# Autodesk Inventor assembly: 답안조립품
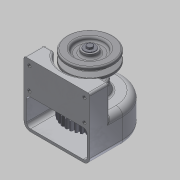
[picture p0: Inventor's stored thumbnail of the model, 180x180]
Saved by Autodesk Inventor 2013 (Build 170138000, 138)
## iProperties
Created: 2015-02
Part Number: 답안조립품
Document SubType Name: Assembly
Designer: Administrator
Author: Administrator
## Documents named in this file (14)
- C:\Users\Administrator\Desktop\450216V1013\답안조립품.iam
- C:\Users\Administrator\Desktop\450216V1013\본체.ipt
- C:\Users\Administrator\Desktop\450216V1013\축커버.ipt
- C:\Users\Administrator\Desktop\450216V1013\베어링 6001.ipt
- C:\Users\Administrator\Desktop\450216V1013\오일실.ipt
- C:\Users\Administrator\Desktop\450216V1013\M3x0.5.ipt
- C:\Users\Administrator\Desktop\450216V1013\축.ipt
- C:\Users\Administrator\Desktop\450216V1013\키4x4.ipt
- C:\Users\Administrator\Desktop\450216V1013\키5x5.ipt
- C:\Users\Administrator\Desktop\450216V1013\스퍼기어.ipt
- C:\Users\Administrator\Desktop\450216V1013\V-벨트풀리.ipt
- C:\Users\Administrator\Desktop\450216V1013\M5x0.8.ipt
- M5x0.8.ipt
- C:\Users\Administrator\Desktop\450216V1013\와샤.ipt
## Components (6 placed, 3 different names)
1. V-벨트풀리:1 — 각도:2, 플러쉬:1, 각도:3
2. M5x0.8:1 — 각도:3
3. M3x0.5:1
4. M3x0.5:2
5. M3x0.5:3
6. M3x0.5:4
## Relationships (3: Angle 2, Flush 1)
- 각도:2 [Angle]: V-벨트풀리:1
- 플러쉬:1 [Flush]: V-벨트풀리:1
- 각도:3 [Angle]: V-벨트풀리:1 ↔ M5x0.8:1
